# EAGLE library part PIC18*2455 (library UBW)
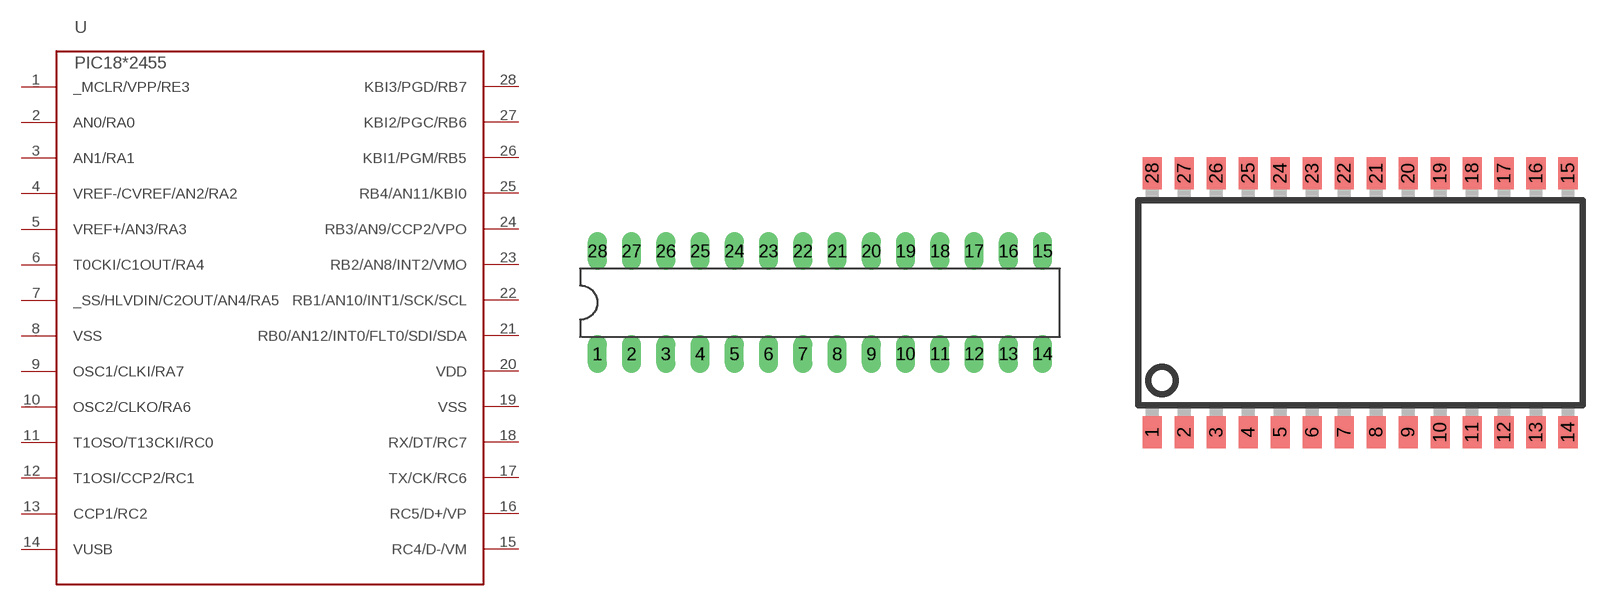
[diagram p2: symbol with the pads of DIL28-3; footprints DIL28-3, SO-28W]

Designator prefix -

## PIC18F2455-I/SP  [DIL28-3]
1  _MCLR/VPP/RE3  in
2  AN0/RA0
3  AN1/RA1
4  VREF-/CVREF/AN2/RA2
5  VREF+/AN3/RA3
6  T0CKI/C1OUT/RA4
7  _SS/HLVDIN/C2OUT/AN4/RA5
8  VSS  pwr
9  OSC1/CLKI/RA7
10  OSC2/CLKO/RA6
11  T1OSO/T13CKI/RC0
12  T1OSI/CCP2/RC1
13  CCP1/RC2
14  VUSB
15  RC4/D-/VM
16  RC5/D+/VP
17  TX/CK/RC6
18  RX/DT/RC7
19  VSS  pwr
20  VDD  pwr
21  RB0/AN12/INT0/FLT0/SDI/SDA
22  RB1/AN10/INT1/SCK/SCL
23  RB2/AN8/INT2/VMO
24  RB3/AN9/CCP2/VPO
25  RB4/AN11/KBI0
26  KBI1/PGM/RB5
27  KBI2/PGC/RB6
28  KBI3/PGD/RB7

## PIC182455-E/SO  [SO-28W]
Pads as for DIL28-3

## Footprint DIL28-3 (pad centres in mm)
Dual In Line package type SP
drill 0.9 long: 1 -16.51,-3.81; 2 -13.97,-3.81; 3 -11.43,-3.81; 4 -8.89,-3.81; 5 -6.35,-3.81; 6 -3.81,-3.81; 7 -1.27,-3.81; 8 1.27,-3.81; 9 3.81,-3.81; 10 6.35,-3.81; 11 8.89,-3.81; 12 11.43,-3.81; 13 13.97,-3.81; 14 16.51,-3.81; 15 16.51,3.81; 16 13.97,3.81; 17 11.43,3.81; 18 8.89,3.81; 19 6.35,3.81; 20 3.81,3.81; 21 1.27,3.81; 22 -1.27,3.81; 23 -3.81,3.81; 24 -6.35,3.81; 25 -8.89,3.81; 26 -11.43,3.81; 27 -13.97,3.81; 28 -16.51,3.81

## Footprint SO-28W (pad centres in mm)
Small Outline Wide Plastic Gull Wing 300-mil body, package type SO
smd 0.762 x 1.27: 1 -7.62,-5.207; 2 -6.35,-5.207; 3 -5.08,-5.207; 4 -3.81,-5.207; 5 -2.54,-5.207; 6 -1.27,-5.207; 7 0,-5.207; 8 1.27,-5.207; 9 2.54,-5.207; 10 3.81,-5.207; 11 5.08,-5.207; 12 6.35,-5.207; 13 7.62,-5.207; 14 8.89,-5.207; 15 8.89,5.08; 16 7.62,5.08; 17 6.35,5.08; 18 5.08,5.08; 19 3.81,5.08; 20 2.54,5.08; 21 1.27,5.08; 22 0,5.08; 23 -1.27,5.08; 24 -2.54,5.08; 25 -3.81,5.08; 26 -5.08,5.08; 27 -6.35,5.08; 28 -7.62,5.08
